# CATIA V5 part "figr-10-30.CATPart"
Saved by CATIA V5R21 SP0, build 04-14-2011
Part number: Part1
Bounding box of the stored display mesh (mm): x -80 to 120, y 0 to 190, z 0 to 170
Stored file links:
  D:\CATIA V5R21 E-RESOURCES\CATIA-V5R21\catia-v5r21-prt\c10-catia-v5r20-prt\c10-catia-v5r21-figr-10-30.CATPart
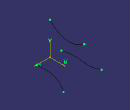
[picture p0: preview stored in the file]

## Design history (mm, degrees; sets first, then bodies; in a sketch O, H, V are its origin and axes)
Set1
  Sketch1 on xy-plane, origin (0, 0, 0), H (1, 0, 0), V (0, 1, 0)
    spline S1 through (-60, 0) (-70, 70) (-70, 170) (-80, 190)
  Sketch2 on yz-plane, origin (0, 0, 0), H (0, 1, 0), V (0, 0, 1)
    spline S1 through (0, 170) (100, 120) (180, 150)
  Sketch3 on xy-plane, origin (0, 0, 0), H (1, 0, 0), V (0, 1, 0)
    spline S1 through (70, 0) (70, 80) (120, 190)
Body1 (main body)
